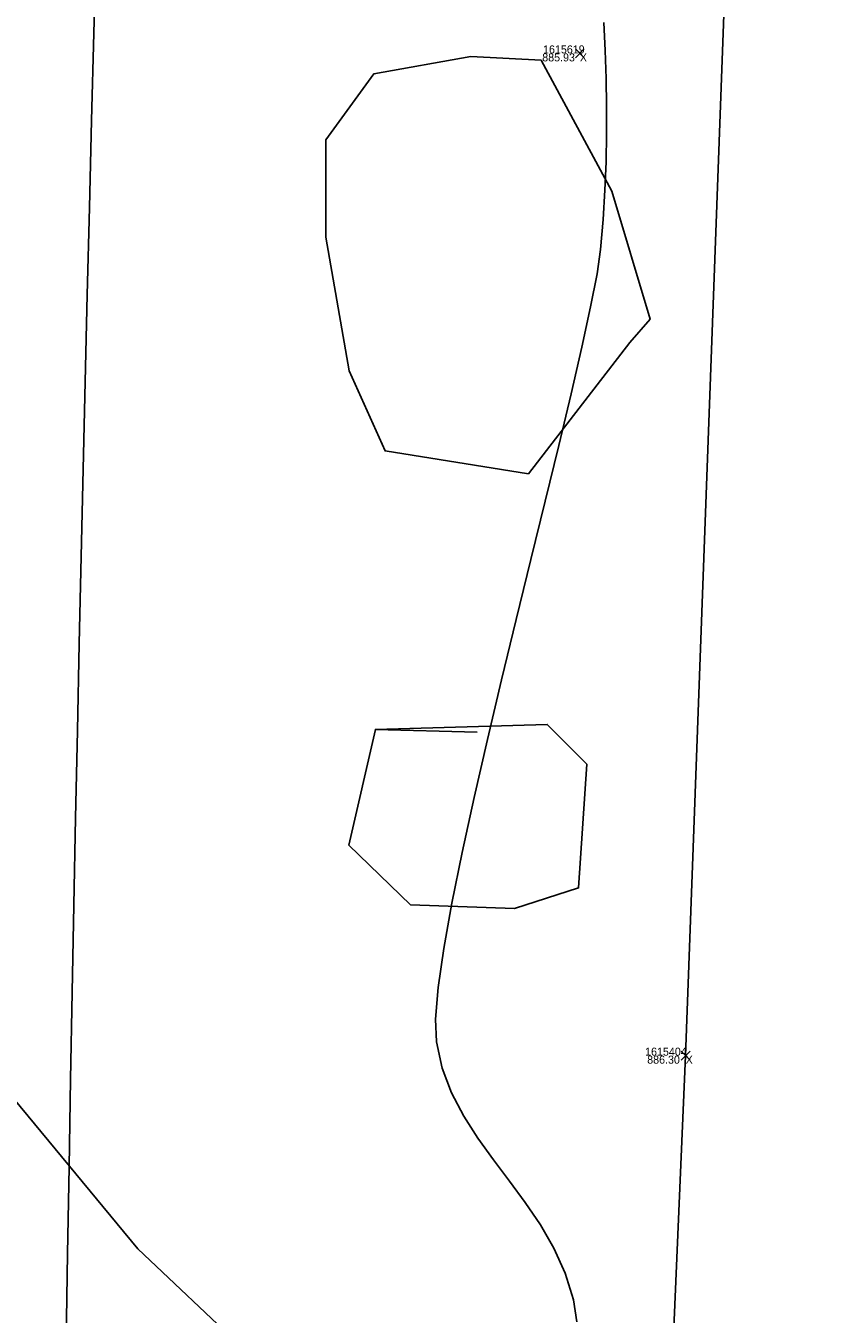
# Model space of a CAD drawing. Extents: x 1957117 to 1971063, y 701601 to 715861.
# Drawn here: x 1962770.2 to 1962805.2, y 703191.3 to 703247.6 of the extents above; entities that cross this region are included whole.
import ezdxf

# ---------------------------------------------------------------- set-up
doc = ezdxf.new("R2010")
doc.units = 0
for name, color, linetype in [('AP_X_Lights', 7, 'Continuous'), ('DT_X_Contour_Minor', 7, 'Continuous'), ('DT_X_TIN_Hull', 7, 'Continuous'), ('GE_X_CL_20', 7, 'Continuous'), ('PV_P_Shoulder', 7, 'Continuous'), ('RS_Raster1', 7, 'Continuous'), ('RW_X_Esmt_RR', 7, 'Continuous'), ('SC_Scratch1', 7, 'Continuous'), ('VG_X_Tree_Line_Rt', 7, 'Continuous')]:
    doc.layers.add(name, color=color, linetype=linetype)

msp = doc.modelspace()

# ---------------------------------------------------------------- linework, layer by layer
at = {"layer": 'AP_X_Lights'}
for p, q in [((1962794.225, 703246.212), (1962794.613, 703246.602)), ((1962794.225, 703246.602), (1962794.613, 703246.212)), ((1962798.854, 703202.366), (1962799.242, 703202.756)), ((1962798.854, 703202.756), (1962799.242, 703202.366))]:
    msp.add_line(p, q, dxfattribs=at)
at = {"layer": 'DT_X_Contour_Minor'}
msp.add_lwpolyline([(1962794.294, 703190.916), (1962794.149, 703191.876), (1962793.783, 703193.051), (1962793.288, 703194.139), (1962792.694, 703195.16), (1962792.033, 703196.133), (1962791.336, 703197.075), (1962790.634, 703198.008), (1962789.958, 703198.948), (1962789.34, 703199.916), (1962788.81, 703200.929), (1962788.4, 703202.008), (1962788.141, 703203.171), (1962788.108, 703204.163), (1962788.223, 703205.537), (1962788.467, 703207.245), (1962788.823, 703209.234), (1962789.271, 703211.455), (1962789.795, 703213.858), (1962790.375, 703216.391), (1962790.994, 703219.005), (1962791.634, 703221.648), (1962792.276, 703224.272), (1962792.903, 703226.824), (1962793.496, 703229.255), (1962794.038, 703231.514), (1962794.51, 703233.551), (1962794.893, 703235.316), (1962795.171, 703236.758), (1962795.325, 703237.826), (1962795.439, 703239.14), (1962795.52, 703240.417), (1962795.569, 703241.664), (1962795.591, 703242.89), (1962795.589, 703244.104), (1962795.565, 703245.314), (1962795.522, 703246.53), (1962795.464, 703247.759)], dxfattribs=at)
msp.add_lwpolyline([(1962794.294, 703190.916), (1962794.149, 703191.876), (1962793.783, 703193.051), (1962793.288, 703194.139), (1962792.694, 703195.16), (1962792.033, 703196.133), (1962791.336, 703197.075), (1962790.634, 703198.008), (1962789.958, 703198.948), (1962789.34, 703199.916), (1962788.81, 703200.929), (1962788.4, 703202.008), (1962788.141, 703203.171), (1962788.108, 703204.163), (1962788.223, 703205.537), (1962788.467, 703207.245), (1962788.823, 703209.234), (1962789.271, 703211.455), (1962789.795, 703213.858), (1962790.375, 703216.391), (1962790.994, 703219.005), (1962791.634, 703221.648), (1962792.276, 703224.272), (1962792.903, 703226.824), (1962793.496, 703229.255), (1962794.038, 703231.514), (1962794.51, 703233.551), (1962794.893, 703235.316), (1962795.171, 703236.758), (1962795.325, 703237.826), (1962795.439, 703239.14), (1962795.52, 703240.417), (1962795.569, 703241.664), (1962795.591, 703242.89), (1962795.589, 703244.104), (1962795.565, 703245.314), (1962795.522, 703246.53), (1962795.464, 703247.759)], dxfattribs=at)
at = {"layer": 'DT_X_TIN_Hull'}
msp.add_lwpolyline([(1962775.888, 702647.495), (1962778.042, 702697.695), (1962777.816, 702751.499), (1962781.995, 702801.383), (1962785.825, 702901.705), (1962784.091, 702949.602), (1962790.202, 702996.414), (1962788.727, 703101.535), (1962796.63, 703146.099), (1962799.048, 703202.561), (1962802.594, 703299.072), (1962804.686, 703399.836), (1962817.962, 703593.874)], dxfattribs=at)
at = {"layer": 'GE_X_CL_20'}
msp.add_arc((1968466.781, 702923.066), 5729.578, 166.495347, 177.813939, dxfattribs=at)
at = {"layer": 'RW_X_Esmt_RR'}
msp.add_arc((1968485.769, 703097.688), 5714.578, 174.674821, 179.571005, dxfattribs=at)
at = {"layer": 'VG_X_Tree_Line_Rt'}
for points in [[(1962796.603, 703233.766), (1962792.168, 703228.019), (1962785.897, 703229.02), (1962784.323, 703232.519), (1962783.3, 703238.373), (1962783.299, 703242.625), (1962785.401, 703245.51), (1962789.653, 703246.266), (1962792.72, 703246.11), (1962795.821, 703240.385), (1962797.499, 703234.775), (1962796.603, 703233.766)], [(1962785.474, 703216.833), (1962792.994, 703217.05), (1962794.723, 703215.309), (1962794.368, 703209.899), (1962791.558, 703209.001), (1962787.009, 703209.167), (1962784.308, 703211.775), (1962785.474, 703216.833), (1962789.931, 703216.707)], [(1962780.954, 703176.308), (1962781.397, 703178.212), (1962780.67, 703184.215), (1962779.649, 703189.79), (1962775.075, 703194.112), (1962767.832, 703202.856), (1962761.18, 703197.08), (1962756.219, 703195.837), (1962749.418, 703193.097), (1962741.684, 703193.98), (1962739.099, 703183.893), (1962739.265, 703177.773), (1962742.517, 703174.328), (1962748.535, 703171.129), (1962752.923, 703172.317), (1962760.782, 703172.353), (1962770.523, 703172.31), (1962780.954, 703176.308)]]:
    msp.add_lwpolyline(points, dxfattribs=at)

# ---------------------------------------------------------------- texts
at = {"layer": 'PV_P_Shoulder'}
for s, p in [('885.93', (1962792.774, 703246.057)), ('886.30', (1962797.367, 703202.211))]:
    msp.add_text(s, height=0.35, dxfattribs=at).set_placement(p)
at = {"layer": 'RS_Raster1'}
for s, p in [('1615619', (1962792.81, 703246.407)), ('1615404', (1962797.276, 703202.561))]:
    msp.add_text(s, height=0.35, dxfattribs=at).set_placement(p)
at = {"layer": 'SC_Scratch1'}
for p in [(1962794.419, 703246.057), (1962799.048, 703202.211)]:
    msp.add_text('X', height=0.35, dxfattribs=at).set_placement(p)

doc.saveas('drawing.dxf')
